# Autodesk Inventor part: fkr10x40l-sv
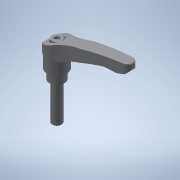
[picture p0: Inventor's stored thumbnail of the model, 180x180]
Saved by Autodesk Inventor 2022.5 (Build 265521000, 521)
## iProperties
Created: 2017-09
Part Number: fkr10x40l-sv
Material: 一般
Document SubType Name: Modeling
Designer: imaocorp
Density: 1 g/cm^3
Appearance: 既定
Author: imaocorp
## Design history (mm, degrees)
node "fkr10x40l-sv.x_t1"
node "fkr10x40l-sv"
node "Base1"
